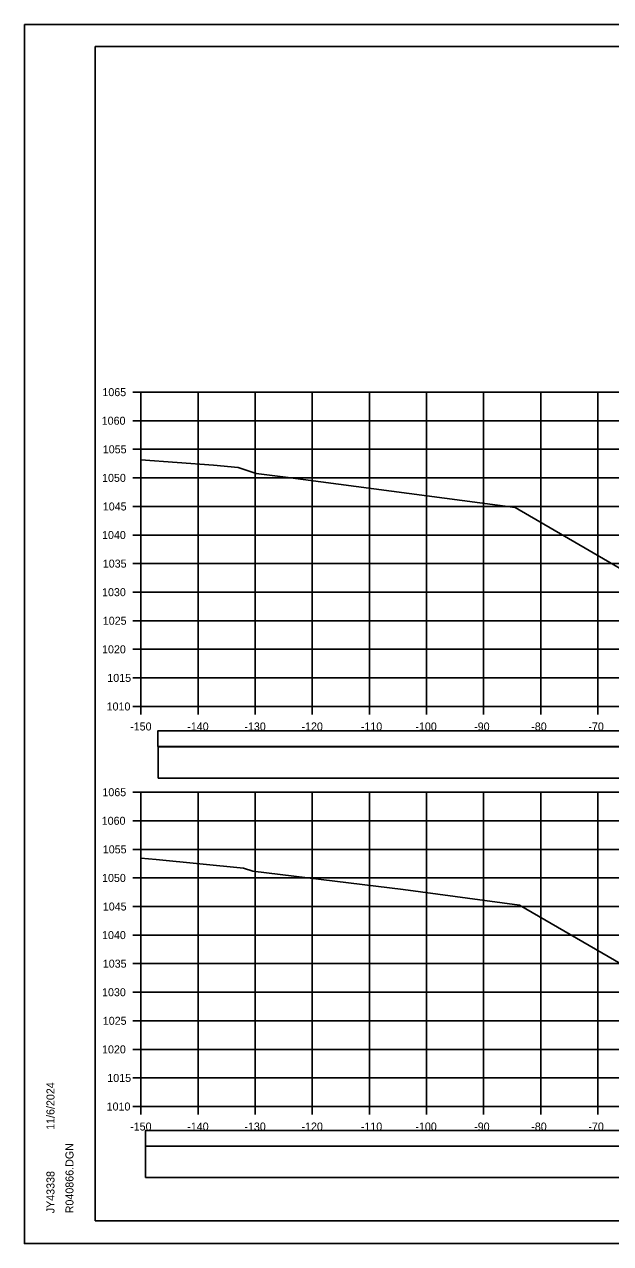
# Model space of a CAD drawing. Extents: x 1370565 to 1374448, y 301010 to 304637.
# Drawn here: x 1370564.6 to 1370667.3, y 302077.2 to 302290.5 of the extents above; entities that cross this region are included whole.
import ezdxf

# ---------------------------------------------------------------- set-up
doc = ezdxf.new("R2010")
doc.units = 0
for name, color, linetype in [('R_Axis', 7, 'Continuous'), ('R_Axis Annot', 7, 'Continuous'), ('R_Border', 7, 'Continuous'), ('R_Drive', 7, 'Continuous'), ('R_Exist Surface', 7, 'Continuous'), ('R_Fin Surface', 7, 'Continuous'), ('R_Grid', 7, 'Continuous'), ('R_No Plot', 7, 'Continuous')]:
    doc.layers.add(name, color=color, linetype=linetype)

msp = doc.modelspace()

# ---------------------------------------------------------------- linework, layer by layer
at = {"layer": 'R_Axis'}
for p, q in [((1370583.63, 302226.17), (1370585.03, 302226.17)), ((1370585.03, 302171.17), (1370585.03, 302226.17)), ((1370583.63, 302221.17), (1370585.03, 302221.17)), ((1370583.63, 302216.17), (1370585.03, 302216.17)), ((1370583.63, 302211.17), (1370585.03, 302211.17)), ((1370583.63, 302206.17), (1370585.03, 302206.17)), ((1370583.63, 302201.17), (1370585.03, 302201.17)), ((1370583.63, 302196.17), (1370585.03, 302196.17)), ((1370583.63, 302191.17), (1370585.03, 302191.17)), ((1370583.63, 302186.17), (1370585.03, 302186.17)), ((1370583.63, 302181.17), (1370585.03, 302181.17)), ((1370583.63, 302176.17), (1370585.03, 302176.17)), ((1370583.63, 302171.17), (1370585.03, 302171.17)), ((1370585.03, 302171.17), (1370885.03, 302171.17)), ((1370585.03, 302169.77), (1370585.03, 302171.17)), ((1370595.03, 302169.77), (1370595.03, 302171.17)), ((1370605.03, 302169.77), (1370605.03, 302171.17)), ((1370615.03, 302169.77), (1370615.03, 302171.17)), ((1370625.03, 302169.77), (1370625.03, 302171.17)), ((1370635.03, 302169.77), (1370635.03, 302171.17)), ((1370645.03, 302169.77), (1370645.03, 302171.17)), ((1370655.03, 302169.77), (1370655.03, 302171.17)), ((1370665.03, 302169.77), (1370665.03, 302171.17)), ((1370583.63, 302156.17), (1370585.03, 302156.17)), ((1370585.03, 302101.17), (1370585.03, 302156.17)), ((1370583.63, 302151.17), (1370585.03, 302151.17)), ((1370583.63, 302146.17), (1370585.03, 302146.17)), ((1370583.63, 302141.17), (1370585.03, 302141.17)), ((1370583.63, 302136.17), (1370585.03, 302136.17)), ((1370583.63, 302131.17), (1370585.03, 302131.17)), ((1370583.63, 302126.17), (1370585.03, 302126.17)), ((1370583.63, 302121.17), (1370585.03, 302121.17)), ((1370583.63, 302116.17), (1370585.03, 302116.17)), ((1370583.63, 302111.17), (1370585.03, 302111.17)), ((1370583.63, 302106.17), (1370585.03, 302106.17)), ((1370583.63, 302101.17), (1370585.03, 302101.17)), ((1370585.03, 302101.17), (1370885.03, 302101.17)), ((1370585.03, 302099.77), (1370585.03, 302101.17)), ((1370595.03, 302099.77), (1370595.03, 302101.17)), ((1370605.03, 302099.77), (1370605.03, 302101.17)), ((1370615.03, 302099.77), (1370615.03, 302101.17)), ((1370625.03, 302099.77), (1370625.03, 302101.17)), ((1370635.03, 302099.77), (1370635.03, 302101.17)), ((1370645.03, 302099.77), (1370645.03, 302101.17)), ((1370655.03, 302099.77), (1370655.03, 302101.17)), ((1370665.03, 302099.77), (1370665.03, 302101.17))]:
    msp.add_line(p, q, dxfattribs=at)
at = {"layer": 'R_Border'}
for p, q in [((1370577.03, 302286.63), (1370893.21, 302286.63)), ((1370577.03, 302081.17), (1370577.03, 302286.63)), ((1370577.03, 302081.17), (1370577.03, 302081.17)), ((1370893.21, 302081.17), (1370577.03, 302081.17))]:
    msp.add_line(p, q, dxfattribs=at)
at = {"layer": 'R_Drive'}
for points in [[(1370587.98, 302164.18), (1370886.39, 302164.18), (1370886.39, 302166.89), (1370587.98, 302166.89)], [(1370585.82, 302094.26), (1370884.24, 302094.26), (1370884.24, 302096.97), (1370585.82, 302096.97)], [(1370585.82, 302088.74), (1370884.24, 302088.74), (1370884.24, 302094.26), (1370585.82, 302094.26)]]:
    msp.add_lwpolyline(points, close=True, dxfattribs=at)
at = {"layer": 'R_Exist Surface'}
for points in [[(1370585.03, 302214.34), (1370597.71, 302213.4), (1370602.05, 302212.97), (1370605.19, 302211.94), (1370610.33, 302211.32), (1370650.56, 302205.97), (1370672.13, 302193.46), (1370680.29, 302188.98), (1370682.06, 302189.24), (1370689.97, 302190.43), (1370694.08, 302190.14), (1370700.24, 302189.74), (1370704.19, 302189.35), (1370711.09, 302188.69), (1370717.4, 302187.46), (1370723.5, 302186.26), (1370731.61, 302190.51), (1370737.82, 302193.81), (1370762.6, 302192.19), (1370788.51, 302190.48)], [(1370585.03, 302144.6), (1370587.71, 302144.4), (1370602.96, 302142.88), (1370604.64, 302142.34), (1370630.92, 302139.15), (1370651.32, 302136.42), (1370673.47, 302123.56), (1370680.84, 302119.13), (1370683.8, 302119.57), (1370690.59, 302120.59), (1370692.51, 302120.46), (1370700.85, 302119.9), (1370702.49, 302119.74), (1370711.64, 302118.87), (1370714.28, 302118.36), (1370723.91, 302116.46), (1370736.58, 302123.11), (1370738.32, 302124.03), (1370745.47, 302123.56), (1370788.49, 302120.72)]]:
    msp.add_lwpolyline(points, dxfattribs=at)
at = {"layer": 'R_Fin Surface'}
msp.add_lwpolyline([(1370588.03, 302158.6), (1370886.45, 302158.6), (1370886.45, 302164.13), (1370588.03, 302164.13)], close=True, dxfattribs=at)
at = {"layer": 'R_Grid'}
for p, q in [((1370585.03, 302226.17), (1370885.03, 302226.17)), ((1370585.03, 302171.17), (1370585.03, 302226.17)), ((1370595.03, 302171.17), (1370595.03, 302226.17)), ((1370605.03, 302171.17), (1370605.03, 302226.17)), ((1370615.03, 302171.17), (1370615.03, 302226.17)), ((1370625.03, 302171.17), (1370625.03, 302226.17)), ((1370635.03, 302171.17), (1370635.03, 302226.17)), ((1370645.03, 302171.17), (1370645.03, 302226.17)), ((1370655.03, 302171.17), (1370655.03, 302226.17)), ((1370665.03, 302171.17), (1370665.03, 302226.17)), ((1370585.03, 302221.17), (1370885.03, 302221.17)), ((1370585.03, 302216.17), (1370885.03, 302216.17)), ((1370585.03, 302211.17), (1370885.03, 302211.17)), ((1370585.03, 302206.17), (1370885.03, 302206.17)), ((1370585.03, 302201.17), (1370885.03, 302201.17)), ((1370585.03, 302196.17), (1370885.03, 302196.17)), ((1370585.03, 302191.17), (1370885.03, 302191.17)), ((1370585.03, 302186.17), (1370885.03, 302186.17)), ((1370585.03, 302181.17), (1370885.03, 302181.17)), ((1370585.03, 302176.17), (1370885.03, 302176.17)), ((1370585.03, 302171.17), (1370885.03, 302171.17)), ((1370585.03, 302156.17), (1370885.03, 302156.17)), ((1370585.03, 302101.17), (1370585.03, 302156.17)), ((1370595.03, 302101.17), (1370595.03, 302156.17)), ((1370605.03, 302101.17), (1370605.03, 302156.17)), ((1370615.03, 302101.17), (1370615.03, 302156.17)), ((1370625.03, 302101.17), (1370625.03, 302156.17)), ((1370635.03, 302101.17), (1370635.03, 302156.17)), ((1370645.03, 302101.17), (1370645.03, 302156.17)), ((1370655.03, 302101.17), (1370655.03, 302156.17)), ((1370665.03, 302101.17), (1370665.03, 302156.17)), ((1370585.03, 302151.17), (1370885.03, 302151.17)), ((1370585.03, 302146.17), (1370885.03, 302146.17)), ((1370585.03, 302141.17), (1370885.03, 302141.17)), ((1370585.03, 302136.17), (1370885.03, 302136.17)), ((1370585.03, 302131.17), (1370885.03, 302131.17)), ((1370585.03, 302126.17), (1370885.03, 302126.17)), ((1370585.03, 302121.17), (1370885.03, 302121.17)), ((1370585.03, 302116.17), (1370885.03, 302116.17)), ((1370585.03, 302111.17), (1370885.03, 302111.17)), ((1370585.03, 302106.17), (1370885.03, 302106.17)), ((1370585.03, 302101.17), (1370885.03, 302101.17))]:
    msp.add_line(p, q, dxfattribs=at)
at = {"layer": 'R_No Plot'}
for p, q in [((1370564.63, 302290.52), (1370897.96, 302290.52)), ((1370564.63, 302077.19), (1370897.96, 302077.19))]:
    msp.add_line(p, q, dxfattribs=at)
for points in [[(1370564.62, 302290.52), (1370897.96, 302290.52), (1370897.96, 302077.18), (1370564.62, 302077.18)], [(1370810.95, 302286.63), (1370830.57, 302286.63), (1370830.57, 302276.75), (1370846.68, 302276.75), (1370869.88, 302276.75), (1370869.88, 302244.08), (1370893.09, 302244.08), (1370893.21, 302081.17), (1370577.03, 302081.17), (1370577.03, 302286.63)]]:
    msp.add_lwpolyline(points, close=True, dxfattribs=at)

# ---------------------------------------------------------------- texts
at = {"layer": 'R_Axis Annot'}
for s, p in [('1065', (1370578.28, 302225.47)), ('1060', (1370578.16, 302220.47)), ('1055', (1370578.35, 302215.47)), ('1050', (1370578.22, 302210.47)), ('1045', (1370578.35, 302205.47)), ('1040', (1370578.22, 302200.47)), ('1035', (1370578.35, 302195.47)), ('1030', (1370578.22, 302190.47)), ('1025', (1370578.35, 302185.47)), ('1020', (1370578.22, 302180.47)), ('1015', (1370579.14, 302175.47)), ('1010', (1370579.02, 302170.47)), ('-150', (1370583.14, 302166.97)), ('-140', (1370593.14, 302166.97)), ('-130', (1370603.14, 302166.97)), ('-120', (1370613.14, 302166.97)), ('-110', (1370623.53, 302166.97)), ('-100', (1370633.08, 302166.97)), ('-90', (1370643.37, 302166.97)), ('-80', (1370653.37, 302166.97)), ('-70', (1370663.37, 302166.97)), ('1065', (1370578.28, 302155.47)), ('1060', (1370578.16, 302150.47)), ('1055', (1370578.35, 302145.47)), ('1050', (1370578.22, 302140.47)), ('1045', (1370578.35, 302135.47)), ('1040', (1370578.22, 302130.47)), ('1035', (1370578.35, 302125.47)), ('1030', (1370578.22, 302120.47)), ('1025', (1370578.35, 302115.47)), ('1020', (1370578.22, 302110.47)), ('1015', (1370579.14, 302105.47)), ('1010', (1370579.02, 302100.47)), ('-150', (1370583.14, 302096.97)), ('-140', (1370593.14, 302096.97)), ('-130', (1370603.14, 302096.97)), ('-120', (1370613.14, 302096.97)), ('-110', (1370623.53, 302096.97)), ('-100', (1370633.08, 302096.97)), ('-90', (1370643.37, 302096.97)), ('-80', (1370653.37, 302096.97)), ('-70', (1370663.37, 302096.97))]:
    msp.add_text(s, height=1.4, dxfattribs=at).set_placement(p)
at = {"layer": 'R_Border'}
for s, p in [('11/6/2024', (1370569.89, 302097.09)), ('R040866.DGN', (1370573.22, 302082.49)), ('JY43338', (1370569.89, 302082.49))]:
    msp.add_text(s, height=1.4, rotation=90, dxfattribs=at).set_placement(p)

doc.saveas('drawing.dxf')
